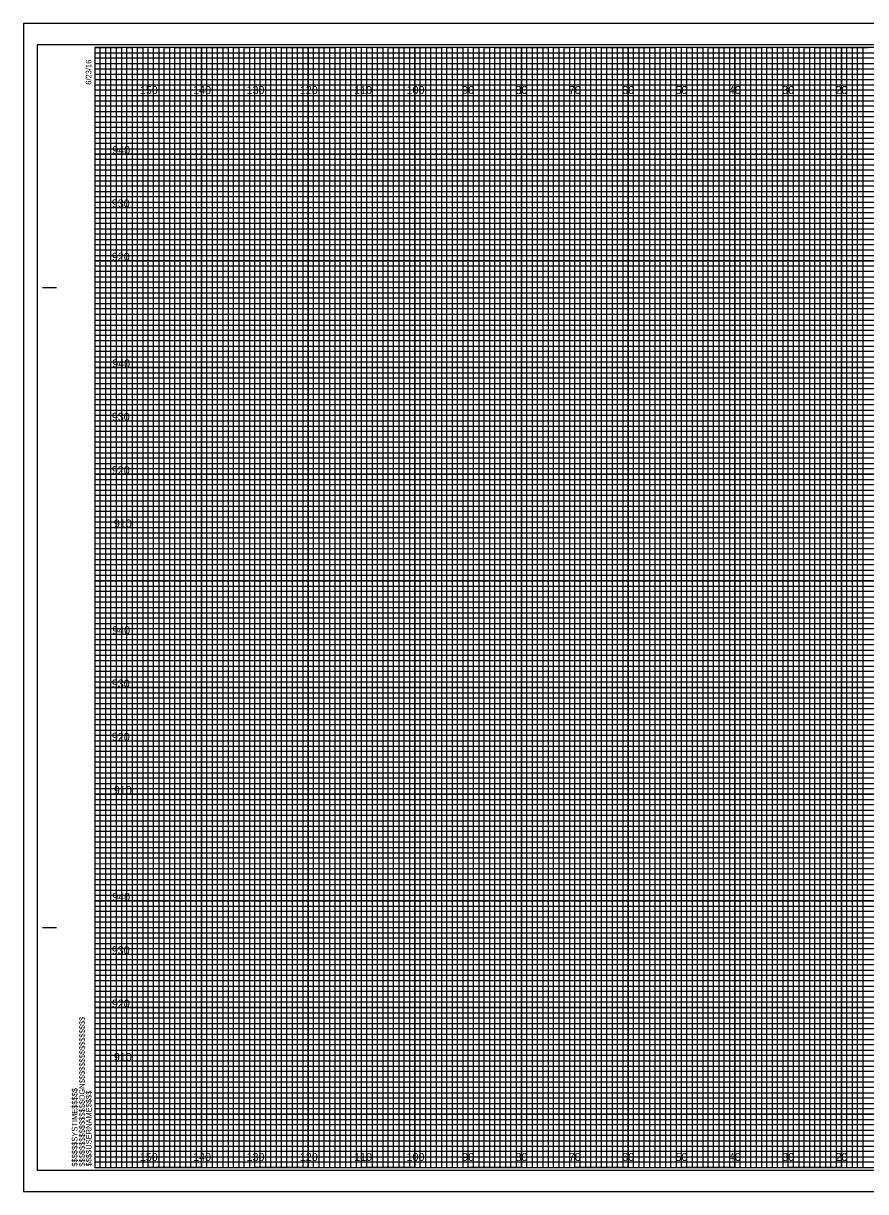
# Model space of a CAD drawing. Extents: x -13 to 323, y -4 to 214.
# Drawn here: x -13.4 to 144.5, y -4.5 to 214.5 of the extents above; entities that cross this region are included whole.
import ezdxf

# ---------------------------------------------------------------- set-up
doc = ezdxf.new("R2010")
doc.units = 0
for name, color, linetype in [('Default', 7, 'Continuous'), ('Prop XS Elevation Labels', 7, 'Continuous'), ('Prop XS Offset Labels', 7, 'Continuous'), ('Sheet Cross Section CELL', 7, 'Continuous'), ('Sheet Cross Section Grid Major CELL', 7, 'Continuous'), ('Sheet Cross Section Grid Middle CELL', 7, 'Continuous'), ('Sheet Cross Section Grid Minor 1 CELL', 7, 'Continuous'), ('Sheet Cross Section Grid Minor 2 CELL', 7, 'Continuous'), ('Sheet Cutting Line CELL', 7, 'Continuous'), ('Sheet DOT Grid CELL', 7, 'Continuous'), ('Sheet Plot Border Inside CELL', 7, 'Continuous'), ('Sheet Plot Border Outside CELL', 7, 'Continuous')]:
    doc.layers.add(name, color=color, linetype=linetype)

msp = doc.modelspace()

# ---------------------------------------------------------------- linework, layer by layer
at = {"layer": 'Default'}
msp.add_line((0, 80), (0, 70), dxfattribs=at)
at = {"layer": 'Sheet Cross Section CELL'}
for p, q in [((-9.8, 165), (-7.3, 165)), ((-9.7, 165), (-7.2, 165)), ((-9.8, 45), (-7.3, 45)), ((-9.7, 45), (-7.2, 45)), ((0, 0), (0, 0)), ((0, 0), (0, 0)), ((0, 0), (0, 0)), ((0, 0), (0, 0)), ((0, 0), (0, 0)), ((0, 0), (0, 0)), ((0, 0), (0, 0))]:
    msp.add_line(p, q, dxfattribs=at)
msp.add_lwpolyline([(320, 210), (0, 210), (0, 0), (320, 0)], close=True, dxfattribs=at)
at = {"layer": 'Sheet Cross Section Grid Major CELL'}
for p, q in [((10, 210), (0, 210)), ((10, 0), (10, 210)), ((30, 210), (20, 210)), ((20, 210), (20, 0)), ((30, 0), (30, 210)), ((50, 210), (40, 210)), ((40, 210), (40, 0)), ((50, 0), (50, 210)), ((70, 210), (60, 210)), ((60, 210), (60, 0)), ((70, 0), (70, 210)), ((90, 210), (80, 210)), ((80, 210), (80, 0)), ((90, 0), (90, 210)), ((110, 210), (100, 210)), ((100, 210), (100, 0)), ((110, 0), (110, 210)), ((130, 210), (120, 210)), ((120, 210), (120, 0)), ((130, 0), (130, 210)), ((150, 210), (140, 210)), ((140, 210), (140, 0)), ((20, 0), (10, 0)), ((40, 0), (30, 0)), ((60, 0), (50, 0)), ((80, 0), (70, 0)), ((100, 0), (90, 0)), ((120, 0), (110, 0)), ((140, 0), (130, 0))]:
    msp.add_line(p, q, dxfattribs=at)
for points in [[(0, 200), (320, 200), (320, 190), (0, 190)], [(0, 180), (320, 180), (320, 170), (0, 170)], [(0, 160), (320, 160), (320, 150), (0, 150)], [(0, 140), (320, 140), (320, 130), (0, 130)], [(0, 120), (320, 120), (320, 110), (0, 110)], [(0, 100), (320, 100), (320, 90), (0, 90)], [(0, 80), (320, 80), (320, 70), (0, 70)], [(0, 60), (320, 60), (320, 50), (0, 50)], [(0, 40), (320, 40), (320, 30), (0, 30)], [(0, 20), (320, 20), (320, 10), (0, 10)]]:
    msp.add_lwpolyline(points, dxfattribs=at)
at = {"layer": 'Sheet Cross Section Grid Middle CELL'}
for points in [[(0, 210), (5, 210), (5, 0), (15, 0), (15, 210), (25, 210), (25, 0), (35, 0), (35, 210), (45, 210), (45, 0), (55, 0), (55, 210), (65, 210), (65, 0), (75, 0), (75, 210), (85, 210), (85, 0), (95, 0), (95, 210), (105, 210), (105, 0), (115, 0), (115, 210), (125, 210), (125, 0), (135, 0), (135, 210), (145, 210)], [(0, 205), (275, 205)], [(0, 185), (320, 185), (320, 195), (0, 195)], [(0, 165), (320, 165), (320, 175), (0, 175)], [(0, 145), (320, 145), (320, 155), (0, 155)], [(0, 125), (320, 125), (320, 135), (0, 135)], [(0, 105), (320, 105), (320, 115), (0, 115)], [(0, 85), (320, 85), (320, 95), (0, 95)], [(0, 65), (320, 65), (320, 75), (0, 75)], [(0, 45), (320, 45), (320, 55), (0, 55)], [(0, 25), (320, 25), (320, 35), (0, 35)], [(0, 5), (320, 5), (320, 15), (0, 15)]]:
    msp.add_lwpolyline(points, dxfattribs=at)
at = {"layer": 'Sheet Cross Section Grid Minor 1 CELL'}
for p, q in [((0, 209), (260, 209)), ((260, 207.98), (0, 207.98)), ((0, 207.98), (0, 207)), ((0, 207), (260, 207)), ((260, 205.89), (0, 205.89)), ((0, 205.89), (0, 204)), ((0, 204), (320, 204))]:
    msp.add_line(p, q, dxfattribs=at)
for points in [[(0, 203), (270, 203), (320, 203), (320, 202), (0, 202)], [(0, 201), (320, 201), (320, 199), (0, 199)], [(0, 198), (320, 198), (320, 197), (0, 196.98)], [(0, 196), (320, 196), (320, 194), (0, 194)], [(0, 193), (320, 193), (320, 192), (0, 192)], [(0, 191), (320, 191), (320, 189), (0, 189)], [(0, 188), (320, 188), (320, 187), (0, 187)], [(0, 186), (320, 186), (320, 184), (0, 184)], [(0, 183), (320, 183), (320, 182), (0, 182)], [(0, 181), (320, 181), (320, 179), (0, 179)], [(0, 178), (320, 178), (320, 177), (0, 177)], [(0, 176), (320, 176), (320, 173.95), (320, 173), (320, 172), (0, 172)], [(0, 174), (320, 174), (320, 173), (0, 173)], [(0, 171), (320, 171), (320, 169), (0, 169.03)], [(0, 169.03), (320, 169), (320, 168), (0, 168)], [(0, 167), (320, 167), (320, 166), (0, 166)], [(0, 164), (320, 164), (320, 163), (0, 163)], [(0, 162), (320, 162), (320, 161), (0, 161)], [(-0.07, 158.89), (320, 158.89), (320, 157.88), (-0.07, 157.88)], [(0, 157), (320, 157), (320, 156), (0, 156)], [(0, 154), (320, 154), (320, 153), (0, 153)], [(0, 152), (320, 152), (320, 151), (0, 151)], [(0, 149), (320, 149), (320, 148), (0, 148)], [(0, 147), (320, 147), (320, 146), (0, 146)], [(0, 144), (320, 144), (320, 143), (0, 143)], [(0, 142), (320, 142), (320, 141), (0, 141)], [(0, 139), (320, 139), (319.99, 137.98), (0, 138)], [(0, 137), (320, 137), (320, 136), (0, 136)], [(0, 134), (320, 134), (320, 133), (0, 133)], [(0, 132), (320, 132), (320, 131), (0, 131)], [(0, 129), (320, 129), (320, 128), (0, 128)], [(0, 127), (320, 127), (320, 126), (0, 126)], [(0, 124), (320, 124), (320, 123), (0, 123)], [(0, 122), (320, 122), (320, 121), (0, 121)], [(0, 119), (320, 119), (320, 118), (0, 118)], [(0, 116.99), (320.07, 116.91), (320, 116), (0, 116)], [(0, 114), (320, 114), (320, 113), (0, 113)], [(0, 112), (320, 112), (320, 111), (0, 111)], [(0, 109), (320, 109), (320, 108), (0, 108)], [(0, 107), (320, 107), (320, 106), (0, 106)], [(0, 104), (320, 104), (320, 103), (0, 103)], [(0, 102), (320, 102), (320, 101), (0, 101)], [(0, 99), (320, 99), (320, 98), (0, 98)], [(0, 97), (320, 97), (320, 96), (0, 96)], [(0, 94), (320, 94), (320, 93), (0, 93)], [(0, 92), (320, 92), (320, 91), (0, 91)], [(0, 89), (320, 89), (320, 88), (0, 88)], [(0, 87), (320, 87), (320, 86), (0, 86)], [(0, 84), (320, 84), (320, 83), (0, 83)], [(0, 82), (320, 82), (320, 81), (0, 81)], [(0, 79), (320, 79), (319.99, 77.98), (0, 78)], [(0, 77), (320, 77), (320, 76), (0, 76)], [(0, 74), (320, 74), (320, 73), (0, 73)], [(0, 72), (320, 72), (320, 71), (0, 71)], [(0, 69), (320, 69), (320, 68), (0, 68)], [(0, 67), (320, 67), (320, 66), (0, 66)], [(0, 64), (320, 64), (320, 63), (0, 63)], [(0, 62), (320, 62), (320, 61), (0, 61)], [(0, 59), (320, 59), (320, 58), (0, 58)], [(0, 56.99), (320.07, 56.91), (320, 56), (0, 56)], [(0, 54), (320, 54), (320, 53), (0, 53)], [(0, 52), (320, 52), (320, 51), (0, 51)], [(0, 49), (320, 49), (320, 48), (0, 48)], [(0, 47), (320, 47), (320, 46), (0, 46)], [(0, 44), (320, 44), (320, 43), (0, 43)], [(0, 42), (320, 42), (320, 41), (0, 41)], [(0, 39), (320, 39), (320, 38), (0, 38)], [(0, 37), (320, 37), (320, 36), (0, 36)], [(0, 34), (320, 34), (320, 33), (0, 33)], [(0, 32), (320, 32), (320, 31), (0, 31)], [(0, 29), (320, 29), (320, 28), (0, 28)], [(0, 27), (320, 27), (320, 26), (0, 26)], [(0, 24), (320, 24), (320, 23), (0, 23)], [(0, 22), (320, 22), (320, 21), (0, 21)], [(0, 19), (320, 19), (320, 18), (0, 18)], [(0, 17), (320, 17), (320, 16), (0, 16)], [(0, 14), (320, 14), (320, 13), (0, 13)], [(0, 12), (320, 12), (320, 11), (0, 11)], [(0, 9), (320, 9), (320, 8), (0, 8)], [(0, 7), (320, 7), (320, 6), (0, 6)], [(0, 4), (320, 4), (320, 3), (0, 3)], [(0, 2), (320, 2), (320, 1), (0, 1)]]:
    msp.add_lwpolyline(points, dxfattribs=at)
at = {"layer": 'Sheet Cross Section Grid Minor 2 CELL'}
for points in [[(0, 0), (1, 0), (1, 210), (2, 210), (2, 0)], [(2, 0), (3, 0), (3, 210), (4, 210), (4, 0)], [(5, 0), (6, 0), (6, 210), (7, 210), (7, 0)], [(7, 0), (8, 0), (8, 210), (9, 210), (9, 0)], [(10, 0), (11, 0), (11, 210), (12, 210), (12, 0)], [(12, 0), (13, 0), (13, 210), (14, 210), (14, 0)], [(15, 0), (16, 0), (16, 210), (17, 210), (17, 0)], [(17, 0), (18, 0), (18, 210), (19, 210), (19, 0)], [(20, 0), (21, 0), (21, 210), (22, 210), (22, 0)], [(22, 0), (23, 0), (23, 210), (24, 210), (24, 0)], [(25, 0), (26, 0), (26, 210), (27, 210), (27, 0)], [(27, 0), (28, 0), (28, 210), (29, 210), (29, 0)], [(30, 0), (31, 0), (31, 210), (32, 210), (32, 0)], [(32, 0), (33, 0), (33, 210), (34, 210), (34, 0)], [(35, 0), (36, 0), (36, 210), (37, 210), (37, 0)], [(37, 0), (38, 0), (38, 210), (39, 210), (39, 0)], [(40, 0), (41, 0), (41, 210), (42, 210), (42, 0)], [(42, 0), (43, 0), (43, 210), (44, 210), (44, 0)], [(45, 0), (46, 0), (46, 210), (47, 210), (47, 0)], [(47, 0), (48, 0), (48, 210), (49, 210), (49, 0)], [(50, 0), (51, 0), (51, 210), (52, 210), (52, 0)], [(52, 0), (53, 0), (53, 210), (54, 210), (54, 0)], [(55, 0), (56, 0), (56, 210), (57, 210), (57, 0)], [(57, 0), (58, 0), (58, 210), (59, 210), (59, 0)], [(60, 0), (61, 0), (61, 210), (62, 210), (62, 0)], [(62, 0), (63, 0), (63, 210), (64, 210), (64, 0)], [(65, 0), (66, 0), (66, 210), (67, 210), (67, 0)], [(67, 0), (68, 0), (68, 210), (69, 210), (69, 0)], [(70, 0), (71, 0), (71, 210), (72, 210), (72, 0)], [(72, 0), (73, 0), (73, 210), (74, 210), (74, 0)], [(75, 0), (76, 0), (76, 210), (77, 210), (77, 0)], [(77, 0), (78, 0), (78, 210), (79, 210), (79, 0)], [(80, 0), (81, 0), (81, 210), (82, 210), (82, 0)], [(82, 0), (83, 0), (83, 210), (84, 210), (84, 0)], [(85, 0), (86, 0), (86, 210), (87, 210), (87, 0)], [(87, 0), (88, 0), (88, 210), (89, 210), (89, 0)], [(90, 0), (91, 0), (91, 210), (92, 210), (92, 0)], [(92, 0), (93, 0), (93, 210), (94, 210), (94, 0)], [(95, 0), (96, 0), (96, 210), (97, 210), (97, 0)], [(97, 0), (98, 0), (98, 210), (99, 210), (99, 0)], [(100, 0), (101, 0), (101, 210), (102, 210), (102, 0)], [(102, 0), (103, 0), (103, 210), (104, 210), (104, 0)], [(105, 0), (106, 0), (106, 210), (107, 210), (107, 0)], [(107, 0), (108, 0), (108, 210), (109, 210), (109, 0)], [(110, 0), (111, 0), (111, 210), (112, 210), (112, 0)], [(112, 0), (113, 0), (113, 210), (114, 210), (114, 0)], [(115, 0), (116, 0), (116, 210), (117, 210), (117, 0)], [(117, 0), (118, 0), (118, 210), (119, 210), (119, 0)], [(120, 0), (121, 0), (121, 210), (122, 210), (122, 0)], [(122, 0), (123, 0), (123, 210), (124, 210), (124, 0)], [(125, 0), (126, 0), (126, 210), (127, 210), (127, 0)], [(127, 0), (128, 0), (128, 210), (129, 210), (129, 0)], [(130, 0), (131, 0), (131, 210), (132, 210), (132, 0)], [(132, 0), (133, 0), (133, 210), (134, 210), (134, 0)], [(135, 0), (136, 0), (136, 210), (137, 210), (137, 0)], [(137, 0), (138, 0), (138, 210), (139, 210), (139, 0)], [(140, 0), (141, 0), (141, 210), (142, 210), (142, 0)], [(142, 0), (143, 0), (143, 210), (144, 210), (144, 0)]]:
    msp.add_lwpolyline(points, dxfattribs=at)
at = {"layer": 'Sheet Cutting Line CELL'}
for p, q in [((323.3, 214.5), (-13.4, 214.5)), ((-13.4, 214.5), (-13.4, -4.5)), ((-13.4, -4.5), (323.3, -4.5))]:
    msp.add_line(p, q, dxfattribs=at)
at = {"layer": 'Sheet DOT Grid CELL'}
for p, q in [((10, 0), (10, 210)), ((20, 0), (20, 210)), ((30, 0), (30, 210)), ((40, 0), (40, 210)), ((50, 0), (50, 210)), ((60, 0), (60, 210)), ((70, 0), (70, 210)), ((80, 0), (80, 210)), ((90, 0), (90, 210)), ((100, 0), (100, 210)), ((110, 0), (110, 210)), ((120, 0), (120, 210)), ((130, 0), (130, 210)), ((140, 0), (140, 210)), ((0, 200), (320, 200)), ((0, 190), (320, 190)), ((0, 180), (320, 180)), ((0, 170), (320, 170)), ((0, 160), (320, 160)), ((0, 150), (320, 150)), ((0, 140), (320, 140)), ((0, 130), (320, 130)), ((0, 120), (320, 120)), ((0, 110), (320, 110)), ((0, 100), (320, 100)), ((0, 90), (320, 90)), ((0, 80), (320, 80)), ((0, 70), (320, 70)), ((0, 60), (320, 60)), ((0, 50), (320, 50)), ((0, 40), (320, 40)), ((0, 30), (320, 30)), ((0, 20), (320, 20)), ((0, 10), (320, 10))]:
    msp.add_line(p, q, dxfattribs=at)
at = {"layer": 'Sheet Plot Border Inside CELL'}
msp.add_lwpolyline([(-10.8, -0.5), (322.4, -0.5), (322.4, 210.5), (-10.8, 210.5)], close=True, dxfattribs=at)
at = {"layer": 'Sheet Plot Border Outside CELL'}
msp.add_lwpolyline([(-13.4, -4.5), (323.3, -4.5), (323.3, 214.5), (-13.4, 214.5)], close=True, dxfattribs=at)

# ---------------------------------------------------------------- texts
at = {"layer": 'Prop XS Elevation Labels'}
for s, p in [('940', (3.26, 190)), ('930', (3.18, 180)), ('920', (3.19, 170)), ('940', (3.26, 150)), ('930', (3.18, 140)), ('920', (3.19, 130)), ('910', (3.57, 120)), ('940', (3.26, 100)), ('930', (3.18, 90)), ('920', (3.19, 80)), ('910', (3.57, 70)), ('940', (3.26, 50)), ('930', (3.18, 40)), ('920', (3.19, 30)), ('910', (3.57, 20))]:
    msp.add_text(s, height=1.5, dxfattribs=at).set_placement(p)
at = {"layer": 'Prop XS Offset Labels'}
for s, p in [('150', (8.44, 201.25)), ('140', (18.44, 201.25)), ('130', (28.44, 201.25)), ('120', (38.44, 201.25)), ('110', (48.62, 201.25)), ('100', (58.44, 201.25)), ('90', (68.86, 201.25)), ('80', (78.86, 201.25)), ('70', (88.86, 201.25)), ('60', (98.86, 201.25)), ('50', (108.86, 201.25)), ('40', (118.86, 201.25)), ('30', (128.86, 201.25)), ('20', (138.86, 201.25)), ('150', (8.44, 1.25)), ('140', (18.44, 1.25)), ('130', (28.44, 1.25)), ('120', (38.44, 1.25)), ('110', (48.62, 1.25)), ('100', (58.44, 1.25)), ('90', (68.86, 1.25)), ('80', (78.86, 1.25)), ('70', (88.86, 1.25)), ('60', (98.86, 1.25)), ('50', (108.86, 1.25)), ('40', (118.86, 1.25)), ('30', (128.86, 1.25)), ('20', (138.86, 1.25))]:
    msp.add_text(s, height=1.5, dxfattribs=at).set_placement(p)
at = {"layer": 'Sheet Cross Section CELL'}
for s, p in [('6/23/16', (-0.65, 203)), ('$$$$$$$$$$$$$$$$DGN$$$$$$$$$$$$$$$$', (-1.88, 0.18)), ('$$$$$$SYSTIME$$$$$', (-3.26, 0.18)), ('$$$$USERNAME$$$$', (-0.62, 0.23))]:
    msp.add_text(s, height=1.05, rotation=90, dxfattribs=at).set_placement(p)

doc.saveas('drawing.dxf')
